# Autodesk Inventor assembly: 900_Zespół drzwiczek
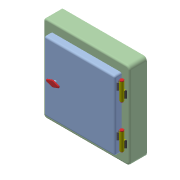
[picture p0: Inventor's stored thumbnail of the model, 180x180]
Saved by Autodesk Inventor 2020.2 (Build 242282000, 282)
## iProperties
Created: 2006-01
Part Number: 900_Zespół drzwiczek
Document SubType Name: Assembly
Designer: F.Stasiak
Manager: www.cadconsulting.pl
Company: Fabian Stasiak CAD Consulting
Author: F.Stasiak
Subject: Zbiór ćwiczeń. Autodesk Inventor 2020. Kurs podstawowy
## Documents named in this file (5)
- C:\2020_Kurs_podstawowy\R7 Prezentacje\800_Zespół drzwiczek.iam
- C:\2020_Kurs_podstawowy\R7 Prezentacje\Komponenty\900_Rama.iam
- C:\2020_Kurs_podstawowy\R7 Prezentacje\Komponenty\900_Drzwi.iam
- C:\2020_Kurs_podstawowy\R7 Prezentacje\Komponenty\900_Trzpień.ipt
- C:\2020_Kurs_podstawowy\R7 Prezentacje\Komponenty\900_Uszczelnienie.ipt
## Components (5 placed, 4 different names)
1. 900_Rama:1 [sub-assembly] — Wstaw:1, Wstaw:2, Kąt:1, Równoległy:2
2. 900_Drzwi:1 [sub-assembly] — Wstaw:1, Wstaw:2, Równoległy:1, Wstaw:3, Wstaw:4, Kąt:1
3. 900_Trzpień:1 — Równoległy:1, Wstaw:3
4. 900_Trzpień:2 — Wstaw:4
5. 900_Uszczelnienie:1 — Równoległy:2
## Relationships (7: Insert 4, Flush 2, Angle 1)
- Wstaw:1 [Insert]: 900_Rama:1 ↔ 900_Drzwi:1
- Wstaw:2 [Insert]: 900_Rama:1 ↔ 900_Drzwi:1
- Równoległy:1 [Flush]: 900_Drzwi:1 ↔ 900_Trzpień:1
- Wstaw:3 [Insert]: 900_Drzwi:1 ↔ 900_Trzpień:1
- Wstaw:4 [Insert]: 900_Drzwi:1 ↔ 900_Trzpień:2
- Kąt:1 [Angle]: 900_Rama:1 ↔ 900_Drzwi:1
- Równoległy:2 [Flush]: 900_Rama:1 ↔ 900_Uszczelnienie:1
